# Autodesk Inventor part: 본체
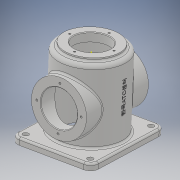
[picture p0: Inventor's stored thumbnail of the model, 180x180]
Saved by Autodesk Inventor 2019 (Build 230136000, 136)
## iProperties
Created: 2020-12
Part Number: 본체
Material: 일반
Document SubType Name: Modeling
Designer: jun-1-7
Density: 1 g/cm^3
Appearance: 기본값
Mass: 457.576 g
Surface Area: 1067.12 cm^2
Volume: 457.576 cm^3
Author: jun-1-7
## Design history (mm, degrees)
sketch "스케치1"
  geometry: L1 (70, 60)-(-70, 60); L2 (-70, 60)-(-70, -60); L3 (-70, -60)-(70, -60); L4 (70, -60)-(70, 60); L5 (70, 60)-(-70, -60); L6 (-70, 60)-(70, -60); 1 further point
  constraints: 12 end point, 2 midpoint, 2 parallel, 1 horizontal, 1 perpendicular
  dimensions: "d0" = 140 distance of L3.end L2.end; "d1" = 120 distance of L2.end L1.end
extrude "돌출1" new body sketch "스케치1" distance "d2" = 10; taper "d3" = 0 deg
sketch "스케치2"
  geometry: C1 r 50 at (0, 0); 1 further point
  constraints: 1 centre point, 1 coincident
  dimensions: "d4" = 100 diameter of C1
extrude "돌출2" join sketch "스케치2" distance "d5" = 110; taper "d6" = 0 deg
sketch "스케치3"
  geometry: C1 r 41 at (0, 0); 1 further point
  constraints: 1 centre point, 1 coincident
  dimensions: "d7" = 82 diameter of C1
extrude "돌출3" join sketch "스케치3" distance "d8" = 5; taper "d9" = 0 deg
sketch "스케치4"
  geometry: 2 further points
  constraints: 1 coincident
hole "구멍1" sketch "스케치4" at (0, 0) diameter "d10" = 54; stored, may be unused: countersink angle "d14" = 90 deg, drill point angle "d16" = 0 deg; dims "d11" = 18, "d12" = 4, "d13" = 2, "d15" = 13
sketch "스케치5"
  geometry: 1 further point
sketch "스케치6"
  geometry: 2 further points
  constraints: 1 coincident
hole "구멍2" sketch "스케치6" at (0, 0) diameter "d17" = 84; stored, may be unused: countersink angle "d21" = 90 deg, drill point angle "d23" = 0 deg; dims "d18" = 18, "d19" = 4, "d20" = 2, "d22" = 112
node "작업 평면1"
sketch "스케치7"
  geometry: L1 (0, 60)-(0, -60) reference; C1 r 41 at (60, 0); 2 further points
  constraints: 1 centre point, 1 horizontal alignment, 1 midpoint
  dimensions: "d25" = 82 diameter of C1; "d26" = 60 distance from line of L1 C1.centre
extrude "돌출4" join sketch "스케치7" stored distance "d27" = 5; taper "d28" = 0 deg
sketch "스케치8"
  geometry: 2 further points
hole "구멍3" sketch "스케치8" at (0, 0) diameter "d29" = 54; stored, may be unused: countersink angle "d33" = 90 deg, drill point angle "d35" = 0 deg; dims "d30" = 18, "d31" = 4, "d32" = 2, "d34" = 112
sketch "스케치9"
  geometry: C1 r 27 at (0, 0) reference; 2 further points
  constraints: 1 vertical alignment
  dimensions: "d36" = 33 distance of C1.centre point (0, 33)
hole "구멍4" sketch "스케치9" at (0, 33) diameter "d37" = 3.242; stored, may be unused: countersink angle "d41" = 90 deg, drill point angle "d43" = 118 deg; dims "d38" = 8, "d39" = 4, "d40" = 2, "d42" = 10
sketch "스케치10"
  geometry: 2 further points
  constraints: 1 vertical alignment
  dimensions: "d47" = 33 distance of point (0, 0) point (0, 33)
hole "구멍5" sketch "스케치10" at (0, 33) diameter "d48" = 3.242; stored, may be unused: countersink angle "d52" = 90 deg, drill point angle "d54" = 118 deg; dims "d49" = 8, "d50" = 4, "d51" = 2, "d53" = 10
fillet "모깎기1" dims "d58" = 12
fillet "모깎기2" dims "d59" = 6
fillet "모깎기3" dims "d60" = 3
fillet "모깎기4" dims "d61" = 3
fillet "모깎기5" dims "d62" = 3
fillet "모깎기6" dims "d63" = 3
chamfer "모따기1" distance "d64" = 1; stored, may be unused: second distance "d65" = 2, angle "d66" = 45 deg
sketch "스케치11"
  geometry: A1 r 9 centre (-58, -48) between (-67, -48) and (-58, -57) reference; 2 further points
  constraints: 1 coincident
hole "구멍6" sketch "스케치11" at (-58, -48) diameter "d67" = 9; stored, may be unused: countersink angle "d71" = 90 deg, drill point angle "d73" = 0 deg; dims "d68" = 8, "d69" = 4, "d70" = 2, "d72" = 10
sketch "스케치12"
  geometry: A1 r 9 centre (58, -48) between (58, -57) and (67, -48) reference; 2 further points
  constraints: 1 coincident
hole "구멍7" sketch "스케치12" at (58, -48) diameter "d74" = 9; stored, may be unused: countersink angle "d78" = 90 deg, drill point angle "d80" = 0 deg; dims "d75" = 8, "d76" = 4, "d77" = 2, "d79" = 10
sketch "스케치13"
  geometry: A1 r 9 centre (58, 48) between (67, 48) and (58, 57) reference; 2 further points
  constraints: 1 coincident
hole "구멍8" sketch "스케치13" at (58, 48) diameter "d81" = 9; stored, may be unused: countersink angle "d85" = 90 deg, drill point angle "d87" = 0 deg; dims "d82" = 8, "d83" = 4, "d84" = 2, "d86" = 10
sketch "스케치14"
  geometry: A1 r 9 centre (-58, 48) between (-58, 57) and (-67, 48) reference; 2 further points
  constraints: 1 coincident
hole "구멍9" sketch "스케치14" at (-58, 48) diameter "d88" = 9; stored, may be unused: countersink angle "d92" = 90 deg, drill point angle "d94" = 0 deg; dims "d89" = 8, "d90" = 4, "d91" = 2, "d93" = 10
node "작업 평면2"
sketch "스케치15"
  geometry: L1 (-58, -10)-(58, -10) reference; 3 further points
  constraints: 1 midpoint, 1 vertical alignment, 1 other
  dimensions: "d95" = 70 distance from line of L1 point (0, 60)
feature "엠보싱1" sketch "스케치15" dims "d0" = 140, "d1" = 120, "d96" = 0.5, "d97" = 0
fillet "모깎기7" dims "d98" = 3
node "솔리드1"
mirror "미러1"
pattern_circular "원형 패턴1" dims angle "d45" = 360 deg
mirror "미러2"
pattern_circular "원형 패턴2" dims angle "d56" = 360 deg
other parameters: "d24" = 59
